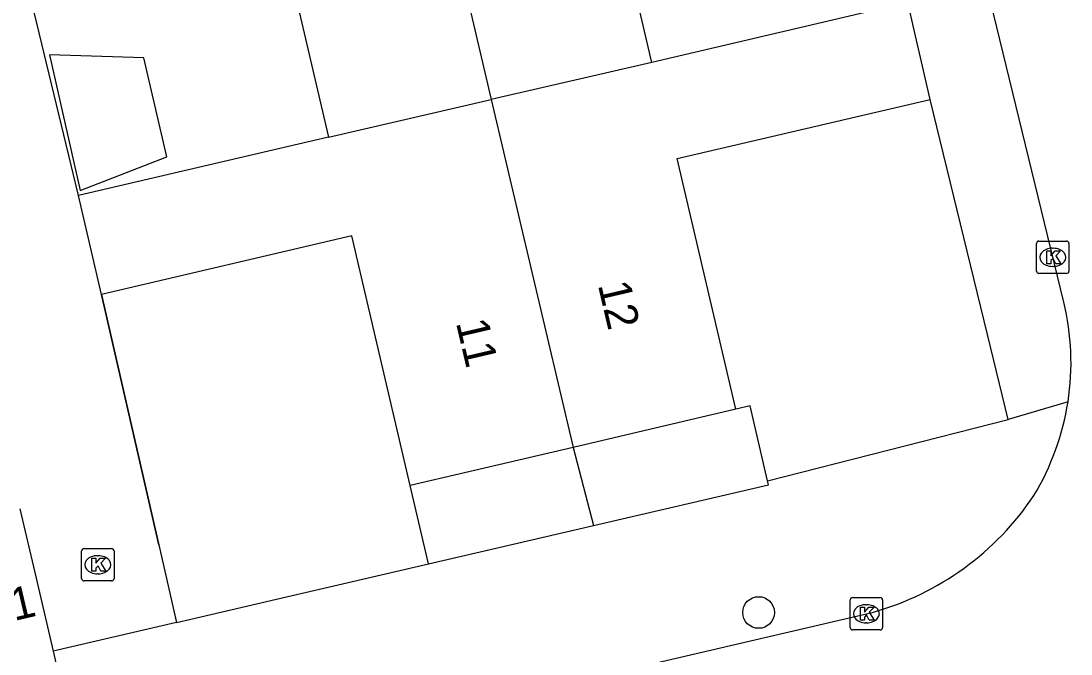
# Model space of a CAD drawing. Extents: x 162990 to 165007, y 383433 to 384336.
# Drawn here: x 164209.76 to 164242.19, y 384045.42 to 384064.99 of the extents above; entities that cross this region are included whole.
import ezdxf

# ---------------------------------------------------------------- set-up
doc = ezdxf.new("R2010")
doc.units = 0
for name, color, linetype in [('IMGEO_Boom', 7, 'Continuous'), ('IMGEO_Kolk', 7, 'Continuous'), ('IMGEO_Muur', 7, 'Continuous'), ('IMGEO_Pand', 7, 'Continuous'), ('IMGEO_Pand_nummerreeks', 7, 'Continuous'), ('IMGEO_Rijbaan_lokaal_open', 7, 'Continuous'), ('IMGEO_Voetpad_open', 7, 'Continuous')]:
    doc.layers.add(name, color=color, linetype=linetype)

msp = doc.modelspace()

# ---------------------------------------------------------------- linework, layer by layer
at = {"layer": 'IMGEO_Boom'}
msp.add_circle((164232.536, 384046.705), 0.489, dxfattribs=at)
at = {"layer": 'IMGEO_Kolk'}
for p, q in [((164241.123, 384057.256), (164241.123, 384058.108)), ((164241.198, 384058.182), (164242.05, 384058.182)), ((164242.124, 384058.108), (164242.124, 384057.256)), ((164241.611, 384057.962), (164241.636, 384057.962)), ((164242.05, 384057.182), (164241.198, 384057.182)), ((164241.634, 384057.402), (164241.609, 384057.402)), ((164211.705, 384048.681), (164212.557, 384048.681)), ((164211.63, 384047.755), (164211.63, 384048.607)), ((164212.118, 384048.461), (164212.143, 384048.461)), ((164212.631, 384048.607), (164212.631, 384047.755)), ((164212.141, 384047.901), (164212.116, 384047.901)), ((164212.557, 384047.681), (164211.705, 384047.681)), ((164235.365, 384046.241), (164235.365, 384047.093)), ((164235.44, 384047.167), (164236.292, 384047.167)), ((164236.366, 384047.093), (164236.366, 384046.241)), ((164235.853, 384046.947), (164235.878, 384046.947)), ((164236.292, 384046.167), (164235.44, 384046.167)), ((164235.876, 384046.387), (164235.851, 384046.387))]:
    msp.add_line(p, q, dxfattribs=at)
for points in [[(164241.123, 384057.256), (164241.123, 384058.108)], [(164241.198, 384058.182), (164242.05, 384058.182)], [(164242.124, 384058.108), (164242.124, 384057.256)], [(164241.444, 384057.882), (164241.567, 384057.882), (164241.567, 384057.731), (164241.697, 384057.882), (164241.861, 384057.882), (164241.715, 384057.731), (164241.868, 384057.482), (164241.716, 384057.482), (164241.631, 384057.646), (164241.567, 384057.579), (164241.567, 384057.482), (164241.444, 384057.482), (164241.444, 384057.882)], [(164242.05, 384057.182), (164241.198, 384057.182)], [(164211.705, 384048.681), (164212.557, 384048.681)], [(164211.63, 384047.755), (164211.63, 384048.607)], [(164211.951, 384048.381), (164212.074, 384048.381), (164212.074, 384048.23), (164212.204, 384048.381), (164212.368, 384048.381), (164212.222, 384048.23), (164212.375, 384047.981), (164212.223, 384047.981), (164212.138, 384048.145), (164212.074, 384048.078), (164212.074, 384047.981), (164211.951, 384047.981), (164211.951, 384048.381)], [(164212.631, 384048.607), (164212.631, 384047.755)], [(164212.557, 384047.681), (164211.705, 384047.681)], [(164235.365, 384046.241), (164235.365, 384047.093)], [(164235.44, 384047.167), (164236.292, 384047.167)], [(164236.366, 384047.093), (164236.366, 384046.241)], [(164235.686, 384046.867), (164235.809, 384046.867), (164235.809, 384046.716), (164235.939, 384046.867), (164236.103, 384046.867), (164235.957, 384046.716), (164236.11, 384046.467), (164235.958, 384046.467), (164235.873, 384046.631), (164235.809, 384046.564), (164235.809, 384046.467), (164235.686, 384046.467), (164235.686, 384046.867)], [(164236.292, 384046.167), (164235.44, 384046.167)]]:
    msp.add_lwpolyline(points, dxfattribs=at)
for centre, start, end in [((164241.2, 384058.106), 91.552, 178.448), ((164241.2, 384058.106), 91.552, 178.448), ((164242.048, 384058.106), 1.552, 88.448), ((164242.048, 384058.106), 1.552, 88.448), ((164241.2, 384057.258), 181.552, 268.448), ((164241.2, 384057.258), 181.552, 268.448), ((164242.048, 384057.258), 271.552, 358.448), ((164242.048, 384057.258), 271.552, 358.448), ((164211.707, 384048.605), 91.552, 178.448), ((164211.707, 384048.605), 91.552, 178.448), ((164212.555, 384048.605), 1.552, 88.448), ((164212.555, 384048.605), 1.552, 88.448), ((164211.707, 384047.757), 181.552, 268.448), ((164211.707, 384047.757), 181.552, 268.448), ((164212.555, 384047.757), 271.552, 358.448), ((164212.555, 384047.757), 271.552, 358.448), ((164235.442, 384047.091), 91.552, 178.448), ((164235.442, 384047.091), 91.552, 178.448), ((164236.29, 384047.091), 1.552, 88.448), ((164236.29, 384047.091), 1.552, 88.448), ((164235.442, 384046.243), 181.552, 268.448), ((164235.442, 384046.243), 181.552, 268.448), ((164236.29, 384046.243), 271.552, 358.448), ((164236.29, 384046.243), 271.552, 358.448)]:
    msp.add_arc(centre, 0.0765, start, end, dxfattribs=at)
for centre, major_axis, ratio, start_param, end_param in [((164241.61, 384057.682), (-0.387, 0.002), 0.722429, 4.712389, 7.853982), ((164241.635, 384057.682), (-0.39, 0.002), 0.717154, 1.570796, 4.712389), ((164212.117, 384048.181), (-0.387, 0.002), 0.722429, 4.712389, 7.853982), ((164212.142, 384048.181), (-0.39, 0.002), 0.717154, 1.570796, 4.712389), ((164235.852, 384046.667), (-0.387, 0.002), 0.722429, 4.712389, 7.853982), ((164235.877, 384046.667), (-0.39, 0.002), 0.717154, 1.570796, 4.712389)]:
    msp.add_ellipse(centre, major_axis=major_axis, ratio=ratio, start_param=start_param, end_param=end_param, dxfattribs=at)
at = {"layer": 'IMGEO_Muur'}
for points in [[(164214.016, 384048.792), (164212.246, 384056.534)], [(164217.957, 384047.185), (164227.443, 384049.39)]]:
    msp.add_lwpolyline(points, dxfattribs=at)
at = {"layer": 'IMGEO_Pand'}
for points in [[(164221.866, 384072.847), (164224.283, 384062.558)], [(164229.244, 384063.707), (164227.544, 384070.977), (164235.434, 384072.823)], [(164209.794, 384066.804), (164217.566, 384068.622), (164219.256, 384061.395)], [(164237.142, 384065.554), (164229.244, 384063.707)], [(164237.841, 384062.563), (164237.142, 384065.554)], [(164210.634, 384063.936), (164211.583, 384059.748), (164214.262, 384060.789), (164213.553, 384063.846), (164210.634, 384063.936)], [(164229.244, 384063.707), (164224.283, 384062.558)], [(164219.256, 384061.395), (164224.283, 384062.558)], [(164224.283, 384062.558), (164226.808, 384051.809)], [(164231.838, 384052.988), (164230.027, 384060.735), (164237.841, 384062.563)], [(164219.256, 384061.395), (164211.531, 384059.588)], [(164212.246, 384056.534), (164211.531, 384059.588)], [(164221.776, 384050.632), (164219.974, 384058.341), (164212.246, 384056.534)], [(164231.838, 384052.988), (164226.808, 384051.809)], [(164232.818, 384050.769), (164232.278, 384053.091), (164231.838, 384052.988)], [(164226.808, 384051.809), (164221.776, 384050.632)], [(164226.808, 384051.809), (164227.443, 384049.39)], [(164222.343, 384048.205), (164221.776, 384050.632)], [(164227.443, 384049.39), (164232.847, 384050.646), (164232.818, 384050.769)], [(164209.723, 384049.905), (164210.224, 384047.764), (164210.751, 384045.51)], [(164222.343, 384048.205), (164227.443, 384049.39)], [(164210.751, 384045.51), (164211.094, 384044.042), (164208.249, 384043.377)]]:
    msp.add_lwpolyline(points, dxfattribs=at)
at = {"layer": 'IMGEO_Rijbaan_lokaal_open'}
for points in [[(164241.962, 384056.296), (164236.928, 384076.981), (164227.517, 384116.826)], [(164227.391, 384044.691), (164236.086, 384046.718)]]:
    msp.add_lwpolyline(points, dxfattribs=at)
for centre, radius, start, end in [((164234.256, 384054.423), 7.931, 351.251, 13.6586), ((164234.261, 384054.428), 7.926, 328.7912, 351.2108), ((164233.683, 384055.23), 8.844, 285.767, 326.2891)]:
    msp.add_arc(centre, radius, start, end, dxfattribs=at)
at = {"layer": 'IMGEO_Voetpad_open'}
for points in [[(164211.531, 384059.588), (164209.794, 384066.804)], [(164240.241, 384052.672), (164239.71, 384054.876), (164237.841, 384062.563)], [(164212.246, 384056.534), (164214.016, 384048.792), (164214.564, 384046.396)], [(164242.094, 384053.217), (164240.241, 384052.672)], [(164232.818, 384050.769), (164240.241, 384052.672)], [(164214.564, 384046.396), (164215.006, 384046.499), (164217.957, 384047.185), (164222.343, 384048.205)], [(164214.564, 384046.396), (164210.751, 384045.51)]]:
    msp.add_lwpolyline(points, dxfattribs=at)

# ---------------------------------------------------------------- texts
at = {"layer": 'IMGEO_Pand_nummerreeks'}
for s, rotation, p in [('12', 283.1606, (164227.571, 384056.833)), ('11', 283.1568, (164223.187, 384055.666)), ('12/G01', 13.2525, (164206.003, 384045.605))]:
    msp.add_text(s, height=1, rotation=rotation, dxfattribs=at).set_placement(p)

doc.saveas('drawing.dxf')
